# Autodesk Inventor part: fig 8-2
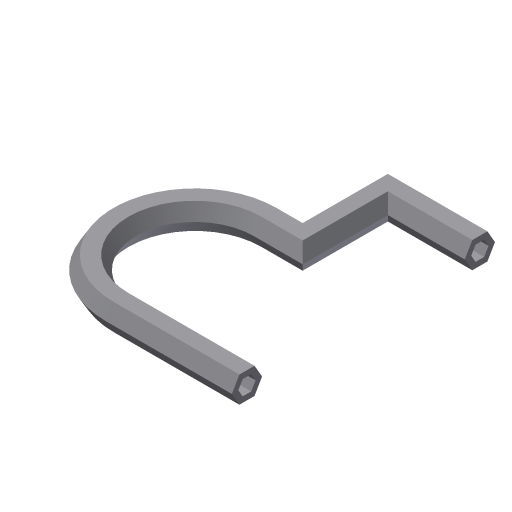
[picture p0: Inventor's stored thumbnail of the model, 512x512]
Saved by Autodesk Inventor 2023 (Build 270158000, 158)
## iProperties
Created: 2004-05
Part Number: fig 8-2
Document SubType Name: Modeling
Designer: CADCIM Technologies
Manufacturer: Standard
Standards Organization: Custom
Density: 1 g/cm^3
Material: Generic
Appearance: Default
Author: CADCIM Technologies
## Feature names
1. Sweep4
## Parameters: d3 = 0, d4 = 0
